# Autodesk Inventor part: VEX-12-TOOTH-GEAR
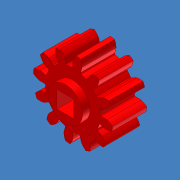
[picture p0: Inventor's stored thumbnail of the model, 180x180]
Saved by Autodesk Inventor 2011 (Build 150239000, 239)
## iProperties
Created: 2007-10
Part Number: VEX-12-TOOTH-GEAR
Document SubType Name: Modeling
Material: ABS Plastic
Density: 1.06 g/cm^3
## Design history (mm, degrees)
feature "Base1"
body "Solid1"
